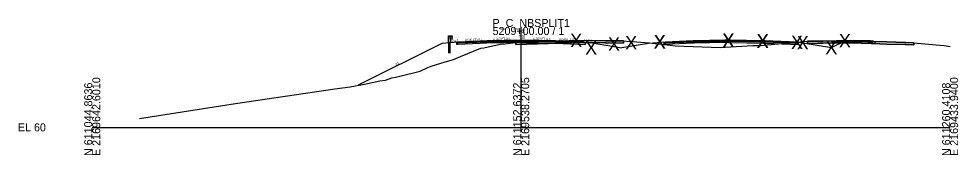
# Model space of a CAD drawing. Extents: x -26 to 1303, y -3010 to 12038.
# Drawn here: x 974.3 to 1302.8, y 5490.3 to 5537.8 of the extents above; entities that cross this region are included whole.
import ezdxf

# ---------------------------------------------------------------- set-up
doc = ezdxf.new("R2010")
doc.units = 0
for name, color, linetype in [('RD_GPK_XS_Cell', 7, 'Continuous'), ('RD_GPK_XS_Text_Node', 7, 'Continuous'), ('RD_PD_Final_TrvlWay', 7, 'Continuous'), ('RD_XS_Base', 7, 'Continuous'), ('RD_XS_ExGround', 7, 'Continuous'), ('RD_XS_ExPaveRet', 7, 'Continuous'), ('RD_XS_GR', 7, 'Continuous'), ('RD_XS_Greenside', 7, 'Continuous'), ('RD_XS_Pave', 7, 'Continuous'), ('RD_XS_PaveOvlay_CP', 7, 'Continuous'), ('RD_XS_TieSlope', 7, 'Continuous'), ('RD_XS_TX_Elev_EX', 7, 'Continuous'), ('RD_XS_TX_Elev_PR', 7, 'Continuous'), ('RD_XS_TX_ShdSlope', 7, 'Continuous'), ('RD_XS_TX_Slope', 7, 'Continuous')]:
    doc.layers.add(name, color=color, linetype=linetype)

msp = doc.modelspace()

# ---------------------------------------------------------------- linework, layer by layer
at = {"layer": 'RD_GPK_XS_Cell'}
for p, q in [((1150, 5500), (1150, 5535)), ((1000, 5500), (1150, 5500)), ((1150, 5500), (1300, 5500))]:
    msp.add_line(p, q, dxfattribs=at)
at = {"layer": 'RD_PD_Final_TrvlWay'}
for p, q in [((1125.11, 5529.53), (1124.61, 5529.49)), ((1124.61, 5529.49), (1124.61, 5525.92)), ((1125.11, 5525.92), (1125.11, 5529.53))]:
    msp.add_line(p, q, dxfattribs=at)
at = {"layer": 'RD_XS_Base'}
for p, q in [((1127.5, 5529.42), (1128, 5529.44)), ((1127.5, 5528.92), (1127.5, 5529.42)), ((1127.5, 5529.42), (1127.5, 5529.42)), ((1128, 5529.44), (1138, 5529.84)), ((1128, 5529.44), (1128, 5529.44)), ((1138, 5529.34), (1128, 5528.94)), ((1138, 5529.84), (1150, 5530.08)), ((1138, 5529.84), (1138, 5529.84)), ((1150, 5529.58), (1138, 5529.34)), ((1138, 5529.34), (1138, 5529.34)), ((1150, 5530.08), (1150, 5530.24)), ((1150, 5530.24), (1150, 5529.58)), ((1150, 5530.08), (1150, 5529.58)), ((1162, 5529.84), (1150, 5530.08)), ((1150, 5530.08), (1150, 5530.08)), ((1150, 5529.58), (1150, 5529.58)), ((1150, 5529.58), (1150, 5529.58)), ((1150, 5529.58), (1162, 5529.34)), ((1172, 5529.44), (1162, 5529.84)), ((1162, 5529.34), (1172.5, 5528.92)), ((1164, 5529.76), (1164, 5529.76)), ((1164, 5529.26), (1164, 5529.26)), ((1172.5, 5529.42), (1172, 5529.44)), ((1172, 5529.44), (1172, 5529.44)), ((1172.5, 5528.92), (1172.5, 5529.42)), ((1172.5, 5529.42), (1172.5, 5529.42)), ((1200.03, 5529.42), (1200.52, 5529.44)), ((1200.03, 5529.41), (1200.03, 5529.42)), ((1200.03, 5528.92), (1200.03, 5529.41)), ((1200.52, 5529.44), (1200.53, 5529.44)), ((1200.53, 5529.44), (1210.16, 5529.83)), ((1210.16, 5529.33), (1200.53, 5528.94)), ((1210.16, 5529.83), (1210.53, 5529.84)), ((1210.53, 5529.34), (1210.16, 5529.33)), ((1210.53, 5529.84), (1221.22, 5530.05)), ((1221.22, 5529.55), (1210.53, 5529.34)), ((1221.22, 5530.05), (1222.53, 5530.08)), ((1222.53, 5529.58), (1221.22, 5529.55)), ((1222.53, 5530.23), (1222.53, 5530.24)), ((1222.53, 5530.24), (1222.53, 5530.2)), ((1222.53, 5530.08), (1222.53, 5530.23)), ((1222.53, 5530.2), (1222.53, 5529.58)), ((1222.53, 5530.08), (1222.53, 5530.05)), ((1222.53, 5530.08), (1222.53, 5530.08)), ((1223.21, 5530.07), (1222.53, 5530.08)), ((1222.53, 5530.08), (1222.53, 5530.08)), ((1222.53, 5530.05), (1222.53, 5529.58)), ((1222.53, 5529.58), (1223.21, 5529.57)), ((1234.53, 5529.84), (1223.21, 5530.07)), ((1223.21, 5529.57), (1234.53, 5529.34)), ((1235.32, 5529.81), (1234.53, 5529.84)), ((1234.53, 5529.34), (1235.36, 5529.31)), ((1246.53, 5529.36), (1235.32, 5529.81)), ((1235.36, 5529.31), (1247.03, 5528.84)), ((1246.57, 5529.36), (1246.53, 5529.36)), ((1247.03, 5529.34), (1246.57, 5529.36)), ((1247.03, 5529.3), (1247.03, 5529.34)), ((1247.03, 5528.84), (1247.03, 5529.3)), ((1258.76, 5529.77), (1259.26, 5529.78)), ((1258.76, 5529.27), (1258.76, 5529.77)), ((1259.26, 5529.28), (1258.76, 5529.27)), ((1259.26, 5529.78), (1261.26, 5529.82)), ((1261.26, 5529.32), (1259.26, 5529.28)), ((1261.26, 5529.82), (1266.26, 5529.92)), ((1266.26, 5529.42), (1261.26, 5529.32)), ((1266.26, 5529.99), (1266.26, 5530.08)), ((1266.26, 5530.08), (1266.26, 5529.73)), ((1266.26, 5529.92), (1266.26, 5529.99)), ((1268.89, 5529.87), (1266.26, 5529.92)), ((1266.26, 5529.92), (1266.26, 5529.42)), ((1266.26, 5529.73), (1266.26, 5529.42)), ((1266.26, 5529.42), (1268.89, 5529.37)), ((1271.26, 5529.82), (1268.89, 5529.87)), ((1268.89, 5529.37), (1271.26, 5529.32)), ((1272.19, 5529.8), (1271.26, 5529.82)), ((1271.26, 5529.32), (1272.42, 5529.3)), ((1273.26, 5529.78), (1272.19, 5529.8)), ((1272.42, 5529.3), (1273.76, 5529.27)), ((1273.49, 5529.77), (1273.26, 5529.78)), ((1273.76, 5529.77), (1273.49, 5529.77)), ((1273.76, 5529.5), (1273.76, 5529.77)), ((1273.76, 5529.27), (1273.76, 5529.5)), ((1128, 5528.94), (1127.5, 5528.92)), ((1127.5, 5528.92), (1127.5, 5528.92)), ((1127.5, 5528.92), (1127.5, 5528.92)), ((1128, 5528.94), (1128, 5528.94)), ((1172.5, 5528.92), (1172.5, 5528.92)), ((1172.5, 5528.92), (1172.5, 5528.92)), ((1200.52, 5528.94), (1200.03, 5528.92)), ((1200.53, 5528.94), (1200.52, 5528.94))]:
    msp.add_line(p, q, dxfattribs=at)
at = {"layer": 'RD_XS_ExGround'}
msp.add_lwpolyline([(1016.52, 5503.14), (1016.57, 5503.06), (1050.09, 5508.31), (1084.83, 5513.47), (1090.22, 5514.14), (1095.21, 5515.08), (1100.56, 5516.17), (1102.55, 5516.49), (1104.77, 5517.22), (1106.1, 5517.52), (1107.53, 5517.88), (1114.73, 5519.55), (1117.32, 5520.83), (1118.5, 5521.36), (1123.47, 5522.83), (1124.67, 5523.22), (1126.39, 5523.72), (1128.82, 5524.73), (1135.87, 5527.57), (1136.95, 5527.76), (1142.67, 5529), (1144.34, 5529.12), (1148.14, 5529.63), (1163.18, 5530.11), (1170.3, 5530.34), (1179.78, 5530.21), (1185.81, 5530.13), (1187.99, 5529.98), (1188.92, 5529.92), (1190.43, 5529.8), (1194.76, 5529.5), (1202.06, 5528.67), (1203.88, 5528.48), (1206.99, 5528.34), (1219.56, 5527.82), (1221.32, 5527.93), (1230.98, 5528.49), (1232.59, 5528.49), (1233.81, 5528.5), (1236.12, 5528.73), (1250.18, 5530.02), (1255.61, 5530.1), (1265.07, 5530.25), (1277.87, 5529.8), (1287.33, 5529.49), (1296.43, 5528.62), (1297.94, 5528.5), (1300, 5528.18)], dxfattribs=at)
at = {"layer": 'RD_XS_ExPaveRet'}
for p, q in [((1163.18, 5530.11), (1148.14, 5529.63)), ((1170.3, 5530.34), (1163.18, 5530.11)), ((1179.78, 5530.21), (1170.3, 5530.34)), ((1185.81, 5530.13), (1179.78, 5530.21)), ((1185.82, 5530.13), (1185.81, 5530.13)), ((1272.95, 5529.98), (1265.07, 5530.25)), ((1287.33, 5529.49), (1284.4, 5529.59))]:
    msp.add_line(p, q, dxfattribs=at)
for points in [[(1185.82, 5530.13), (1185.82, 5530.13), (1185.82, 5529.38), (1185.81, 5529.38), (1179.78, 5529.46), (1179.78, 5529.46), (1170.3, 5529.59), (1170.3, 5529.59), (1163.18, 5529.36), (1163.18, 5529.36), (1148.14, 5528.88), (1148.14, 5528.88), (1148.14, 5528.88), (1148.14, 5529.63), (1148.14, 5529.63), (1148.14, 5529.63), (1148.14, 5529.63), (1163.18, 5530.11), (1163.18, 5530.11), (1170.3, 5530.34), (1170.3, 5530.34), (1179.78, 5530.21), (1179.78, 5530.21), (1185.81, 5530.13), (1185.82, 5530.13)], [(1148.14, 5529.63), (1148.14, 5529.63), (1148.14, 5528.88), (1148.14, 5528.88), (1163.18, 5529.36), (1170.3, 5529.59), (1179.78, 5529.46), (1185.81, 5529.38), (1185.82, 5529.38), (1185.82, 5530.13)], [(1287.33, 5529.49), (1287.33, 5529.03), (1287.33, 5528.74), (1287.33, 5528.74), (1284.4, 5528.84), (1277.87, 5529.05), (1272.95, 5529.23), (1265.07, 5529.5), (1262.51, 5529.46), (1255.61, 5529.35), (1253.7, 5529.32), (1250.18, 5529.27), (1250.18, 5529.48), (1250.18, 5530.02), (1253.7, 5530.07), (1255.61, 5530.1), (1262.51, 5530.21), (1265.07, 5530.25), (1272.95, 5529.98), (1277.87, 5529.8), (1284.4, 5529.59), (1287.33, 5529.49), (1287.33, 5529.49)], [(1255.61, 5530.1), (1253.7, 5530.07), (1250.18, 5530.02)], [(1250.18, 5530.02), (1250.18, 5529.48), (1250.18, 5529.27), (1253.7, 5529.32), (1255.61, 5529.35), (1262.51, 5529.46), (1265.07, 5529.5), (1272.95, 5529.23), (1277.87, 5529.05), (1284.4, 5528.84), (1287.33, 5528.74), (1287.33, 5529.03), (1287.33, 5529.49)], [(1265.07, 5530.25), (1262.51, 5530.21), (1255.61, 5530.1)], [(1284.4, 5529.59), (1277.87, 5529.8), (1272.95, 5529.98)]]:
    msp.add_lwpolyline(points, dxfattribs=at)
at = {"layer": 'RD_XS_GR'}
for points in [[(1125.11, 5531.92), (1125.11, 5529.53), (1124.61, 5529.49), (1124.61, 5531.92), (1124.86, 5531.92), (1125.11, 5531.92)], [(1125.77, 5531.92), (1125.77, 5530.75), (1125.11, 5530.75), (1125.11, 5531.92), (1125.77, 5531.92)], [(1126.04, 5531.63), (1125.77, 5531.92), (1125.77, 5530.75), (1125.77, 5530.75), (1125.77, 5530.75), (1126.04, 5531.05), (1126.04, 5531.05), (1125.77, 5531.34), (1125.77, 5531.34), (1126.04, 5531.63), (1126.04, 5531.63)]]:
    msp.add_lwpolyline(points, dxfattribs=at)
at = {"layer": 'RD_XS_Greenside'}
for p, q in [((1122.29, 5529.3), (1093.03, 5514.67)), ((1174, 5529.6), (1185.22, 5527.73)), ((1194.53, 5529.28), (1185.22, 5527.73)), ((1248.53, 5529.52), (1258.53, 5527.85)), ((1258.53, 5527.85), (1263.27, 5530.22))]:
    msp.add_line(p, q, dxfattribs=at)
at = {"layer": 'RD_XS_Pave'}
for p, q in [((1138, 5530.16), (1128, 5529.76)), ((1138, 5530), (1128, 5529.6)), ((1128, 5529.6), (1138, 5530)), ((1128, 5529.44), (1138, 5529.84)), ((1128, 5529.76), (1128, 5529.76)), ((1128, 5529.76), (1128, 5529.6)), ((1128, 5529.6), (1128, 5529.6)), ((1128, 5529.6), (1128, 5529.44)), ((1128, 5529.6), (1128, 5529.6)), ((1128, 5529.6), (1128, 5529.6)), ((1128, 5529.44), (1128, 5529.44)), ((1128, 5529.44), (1128, 5529.44)), ((1150, 5530.4), (1138, 5530.16)), ((1150, 5530.24), (1138, 5530)), ((1138, 5530), (1150, 5530.24)), ((1138, 5530.16), (1138, 5530.16)), ((1138, 5529.84), (1150, 5530.08)), ((1138, 5530), (1138, 5530)), ((1138, 5530), (1138, 5530)), ((1138, 5529.84), (1138, 5529.84)), ((1162, 5530.16), (1150, 5530.4)), ((1150, 5530.08), (1150, 5530.24)), ((1150, 5530.24), (1162, 5530)), ((1162, 5530), (1150, 5530.24)), ((1150, 5530.24), (1150, 5530.08)), ((1150, 5530.08), (1150, 5530.08)), ((1150, 5530.08), (1150, 5530.08)), ((1150, 5530.08), (1162, 5529.84)), ((1172, 5529.76), (1162, 5530.16)), ((1162, 5530), (1172, 5529.6)), ((1172, 5529.6), (1162, 5530)), ((1162, 5529.84), (1172, 5529.44)), ((1164, 5530.08), (1164, 5530.08)), ((1164, 5529.92), (1164, 5529.92)), ((1164, 5529.92), (1164, 5529.92)), ((1164, 5529.76), (1164, 5529.76)), ((1172, 5529.6), (1172, 5529.76)), ((1172, 5529.76), (1172, 5529.76)), ((1172, 5529.6), (1172, 5529.6)), ((1172, 5529.6), (1172, 5529.6)), ((1172, 5529.44), (1172, 5529.6)), ((1172, 5529.6), (1172, 5529.6)), ((1172, 5529.44), (1172, 5529.44)), ((1172, 5529.44), (1172, 5529.44)), ((1210.16, 5530.14), (1200.53, 5529.76)), ((1210.16, 5529.99), (1200.53, 5529.6)), ((1200.53, 5529.6), (1210.16, 5529.99)), ((1200.53, 5529.44), (1210.16, 5529.83)), ((1200.53, 5529.76), (1200.53, 5529.75)), ((1200.53, 5529.75), (1200.53, 5529.6)), ((1200.53, 5529.6), (1200.53, 5529.59)), ((1200.53, 5529.59), (1200.53, 5529.44)), ((1210.53, 5530.16), (1210.16, 5530.14)), ((1210.53, 5530), (1210.16, 5529.99)), ((1210.16, 5529.99), (1210.53, 5530)), ((1210.16, 5529.83), (1210.53, 5529.84)), ((1221.22, 5530.37), (1210.53, 5530.16)), ((1221.22, 5530.21), (1210.53, 5530)), ((1210.53, 5530), (1221.22, 5530.21)), ((1210.53, 5529.84), (1221.22, 5530.05)), ((1222.53, 5530.4), (1221.22, 5530.37)), ((1222.53, 5530.24), (1221.22, 5530.21)), ((1221.22, 5530.21), (1222.53, 5530.24)), ((1221.22, 5530.05), (1222.53, 5530.08)), ((1223.21, 5530.39), (1222.53, 5530.4)), ((1222.53, 5530.23), (1222.53, 5530.24)), ((1222.53, 5530.24), (1223.21, 5530.23)), ((1223.21, 5530.23), (1222.53, 5530.24)), ((1222.53, 5530.24), (1222.53, 5530.24)), ((1222.53, 5530.24), (1222.53, 5530.24)), ((1222.53, 5530.24), (1222.53, 5530.23)), ((1222.53, 5530.08), (1222.53, 5530.23)), ((1222.53, 5530.23), (1222.53, 5530.08)), ((1222.53, 5530.08), (1222.53, 5530.08)), ((1222.53, 5530.08), (1222.53, 5530.08)), ((1222.53, 5530.08), (1223.21, 5530.07)), ((1234.53, 5530.16), (1223.21, 5530.39)), ((1223.21, 5530.23), (1234.53, 5530)), ((1234.53, 5530), (1223.21, 5530.23)), ((1223.21, 5530.07), (1234.53, 5529.84)), ((1235.32, 5530.13), (1234.53, 5530.16)), ((1234.53, 5530), (1235.32, 5529.97)), ((1235.32, 5529.97), (1234.53, 5530)), ((1234.53, 5529.84), (1235.32, 5529.81)), ((1246.53, 5529.68), (1235.32, 5530.13)), ((1235.32, 5529.97), (1246.53, 5529.52)), ((1246.53, 5529.52), (1235.32, 5529.97)), ((1235.32, 5529.81), (1246.53, 5529.36)), ((1246.53, 5529.67), (1246.53, 5529.68)), ((1246.53, 5529.52), (1246.53, 5529.67)), ((1246.53, 5529.51), (1246.53, 5529.52)), ((1246.53, 5529.36), (1246.53, 5529.51)), ((1260.25, 5530.12), (1259.26, 5530.1)), ((1259.26, 5530.1), (1259.26, 5530.02)), ((1259.26, 5530.02), (1259.26, 5529.94)), ((1261.26, 5529.98), (1259.26, 5529.94)), ((1259.26, 5529.94), (1260.27, 5529.96)), ((1259.26, 5529.94), (1259.26, 5529.78)), ((1259.26, 5529.78), (1261.26, 5529.82)), ((1261.26, 5530.14), (1260.25, 5530.12)), ((1260.27, 5529.96), (1261.26, 5529.98)), ((1263.69, 5530.19), (1261.26, 5530.14)), ((1266.26, 5530.08), (1261.26, 5529.98)), ((1261.26, 5529.98), (1263.69, 5530.03)), ((1261.26, 5529.82), (1266.26, 5529.92)), ((1266.26, 5530.24), (1263.69, 5530.19)), ((1263.69, 5530.03), (1266.26, 5530.08)), ((1268.89, 5530.18), (1266.26, 5530.24)), ((1266.26, 5530.08), (1268.89, 5530.02)), ((1271.26, 5529.98), (1266.26, 5530.08)), ((1266.26, 5530.08), (1266.26, 5529.92)), ((1266.26, 5529.92), (1266.26, 5530.08)), ((1266.26, 5529.92), (1271.26, 5529.82)), ((1271.26, 5530.14), (1268.89, 5530.18)), ((1268.89, 5530.02), (1271.26, 5529.98)), ((1272.19, 5530.12), (1271.26, 5530.14)), ((1271.26, 5529.98), (1272.33, 5529.96)), ((1273.26, 5529.94), (1271.26, 5529.98)), ((1271.26, 5529.82), (1273.26, 5529.78)), ((1273.26, 5530.1), (1272.19, 5530.12)), ((1272.33, 5529.96), (1273.26, 5529.94)), ((1273.26, 5530.01), (1273.26, 5530.1)), ((1273.26, 5529.94), (1273.26, 5530.01)), ((1273.26, 5529.78), (1273.26, 5529.94))]:
    msp.add_line(p, q, dxfattribs=at)
at = {"layer": 'RD_XS_PaveOvlay_CP'}
for p, q in [((1128, 5529.76), (1138, 5530.16)), ((1138, 5530.16), (1150, 5530.4)), ((1150, 5530.4), (1162, 5530.16)), ((1162, 5530.16), (1172, 5529.76)), ((1210.16, 5530.14), (1200.53, 5529.76)), ((1210.53, 5530.16), (1210.16, 5530.14)), ((1221.22, 5530.37), (1210.53, 5530.16)), ((1222.53, 5530.4), (1221.22, 5530.37)), ((1223.21, 5530.39), (1222.53, 5530.4)), ((1234.53, 5530.16), (1223.21, 5530.39)), ((1235.32, 5530.13), (1234.53, 5530.16)), ((1246.53, 5529.68), (1235.32, 5530.13)), ((1259.26, 5530.1), (1261.26, 5530.14)), ((1261.26, 5530.14), (1266.26, 5530.24)), ((1266.26, 5530.24), (1271.26, 5530.14)), ((1271.26, 5530.14), (1273.26, 5530.1))]:
    msp.add_line(p, q, dxfattribs=at)
at = {"layer": 'RD_XS_TieSlope'}
for p, q in [((1128, 5529.76), (1122.29, 5529.3)), ((1172, 5529.76), (1174, 5529.6)), ((1200.53, 5529.76), (1194.53, 5529.28)), ((1246.53, 5529.68), (1248.53, 5529.52))]:
    msp.add_line(p, q, dxfattribs=at)

# ---------------------------------------------------------------- texts
at = {"layer": 'RD_GPK_XS_Cell'}
for s, p in [('P_C_NBSPLIT1', (1140, 5535)), ('5209+00.00 / 1', (1140, 5532.2)), ('EL 60', (974, 5498.6))]:
    msp.add_text(s, height=2.8, dxfattribs=at).set_placement(p)
for s, p in [('E 2169642.6010', (1002.8, 5490)), ('E 2169538.2705', (1152.8, 5490)), ('E 2169433.9400', (1302.8, 5490)), ('N 611044.8636', (1000, 5490)), ('N 611152.6372', (1150, 5490)), ('N 611260.4108', (1300, 5490))]:
    msp.add_text(s, height=2.8, rotation=90, dxfattribs=at).set_placement(p)
at = {"layer": 'RD_GPK_XS_Text_Node'}
for p in [(1167.15, 5527.97), (1220.37, 5528.06), (1220.37, 5527.9), (1232.37, 5527.82), (1261.11, 5527.88), (1172.37, 5525.36), (1180.37, 5526.69), (1186.37, 5527.17), (1196.37, 5527.57), (1196.37, 5527.42), (1232.37, 5527.66), (1244.37, 5527.34), (1246.37, 5527.18), (1256.37, 5525.51)]:
    msp.add_text('X', height=4.69, dxfattribs=at).set_placement(p)
at = {"layer": 'RD_XS_TX_Elev_EX'}
msp.add_text('89.69', height=0.6, rotation=90, dxfattribs=at).set_placement((1149.78, 5531.3))
at = {"layer": 'RD_XS_TX_Elev_PR'}
msp.add_text('90.40', height=1, rotation=90, dxfattribs=at).set_placement((1151.29, 5530.75))
at = {"layer": 'RD_XS_TX_ShdSlope'}
for rotation, p in [(4.5739, (1125.26, 5529.73)), (355.4261, (1171.92, 5530.07))]:
    msp.add_text('12.5:1', height=0.75, rotation=rotation, dxfattribs=at).set_placement(p)
at = {"layer": 'RD_XS_TX_Slope'}
for s, rotation, p in [('0.040 FT./FT.', 2.2906, (1130.31, 5530.11)), ('0.020 FT./FT.', 1.1458, (1140.25, 5530.46)), ('0.020 FT./FT.', 358.8542, (1154.22, 5530.55)), ('0.040 FT./FT.', 357.7094, (1163.26, 5530.36)), ('6:1', 350.5377, (1179.13, 5529.17)), ('2:1', 26.5651, (1106.13, 5521.56))]:
    msp.add_text(s, height=0.75, rotation=rotation, dxfattribs=at).set_placement(p)

doc.saveas('drawing.dxf')
